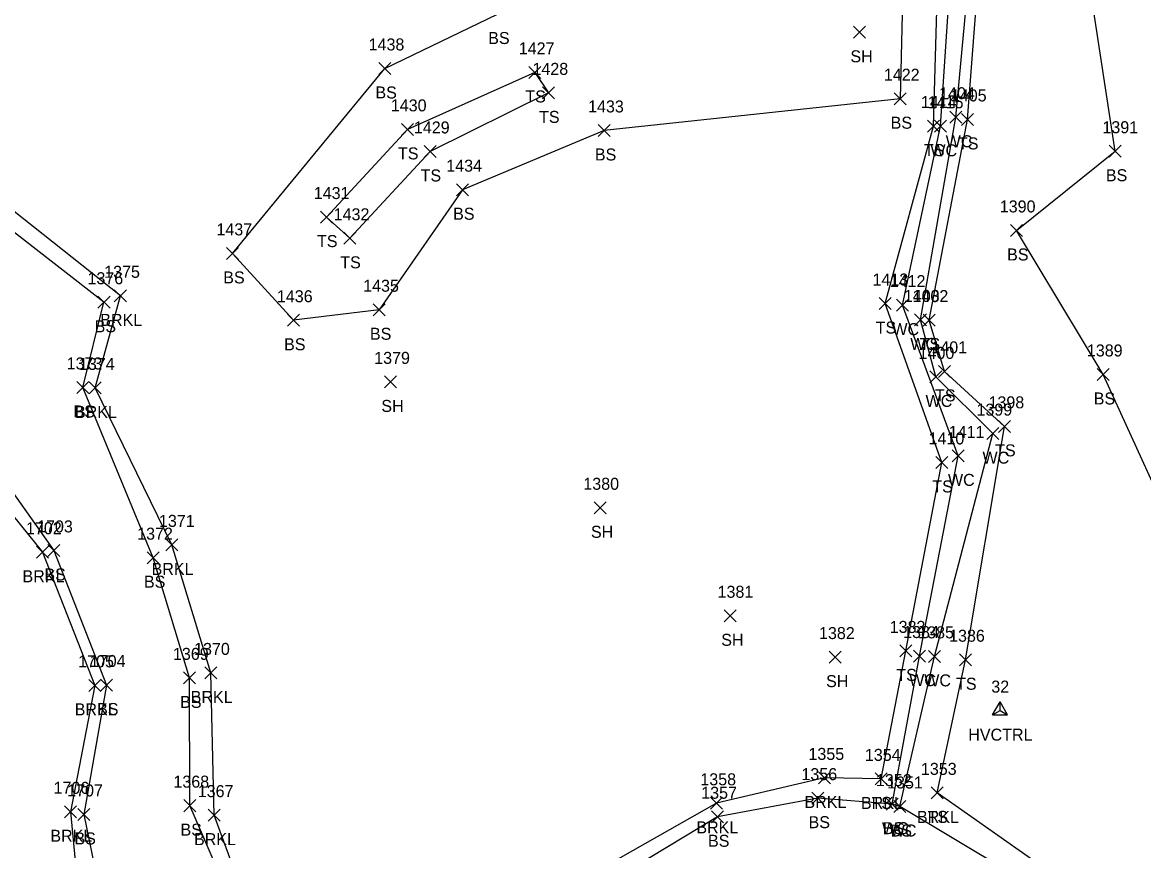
# Model space of a CAD drawing. Extents: x 1754529 to 1755810, y 621660 to 624656.
# Drawn here: x 1755027.6 to 1755214.3, y 623948.9 to 624086.9 of the extents above; entities that cross this region are included whole.
import ezdxf

# ---------------------------------------------------------------- set-up
doc = ezdxf.new("R2010")
doc.units = 0
for name, color, linetype in [('C_A', 7, 'Continuous'), ('C_I', 7, 'Continuous'), ('CPSM', 7, 'Continuous'), ('L_A', 7, 'Continuous'), ('L_I', 7, 'Continuous'), ('L_TIC', 7, 'Continuous'), ('LAWE', 7, 'Continuous'), ('LELB', 7, 'Continuous')]:
    doc.layers.add(name, color=color, linetype=linetype)

msp = doc.modelspace()

# ---------------------------------------------------------------- linework, layer by layer
at = {"layer": 'CPSM'}
for p, q in [((1755189.18, 623971.5), (1755190.43, 623973.67)), ((1755191.68, 623971.5), (1755190.43, 623973.67)), ((1755190.43, 623972.22), (1755190.43, 623973.67)), ((1755189.18, 623971.5), (1755190.43, 623972.22)), ((1755189.18, 623971.5), (1755191.68, 623971.5)), ((1755190.43, 623972.22), (1755190.43, 623972.22)), ((1755190.43, 623972.22), (1755191.68, 623971.5))]:
    msp.add_line(p, q, dxfattribs=at)
at = {"layer": 'L_TIC'}
for points in [[(1755166.02, 624084.22), (1755168.02, 624086.22)], [(1755168.02, 624084.22), (1755166.02, 624086.22)], [(1755086.97, 624078.2), (1755088.97, 624080.2)], [(1755088.97, 624078.2), (1755086.97, 624080.2)], [(1755111.97, 624077.54), (1755113.97, 624079.54)], [(1755113.97, 624077.54), (1755111.97, 624079.54)], [(1755111.97, 624077.54), (1755113.97, 624079.54)], [(1755113.97, 624077.54), (1755111.97, 624079.54)], [(1755114.25, 624074.13), (1755116.25, 624076.13)], [(1755116.25, 624074.13), (1755114.25, 624076.13)], [(1755172.76, 624073.16), (1755174.76, 624075.16)], [(1755174.76, 624073.16), (1755172.76, 624075.16)], [(1755182.05, 624070.07), (1755184.05, 624072.07)], [(1755184.05, 624070.07), (1755182.05, 624072.07)], [(1755184, 624069.71), (1755186, 624071.71)], [(1755186, 624069.71), (1755184, 624071.71)], [(1755090.76, 624068.05), (1755092.76, 624070.05)], [(1755092.76, 624068.05), (1755090.76, 624070.05)], [(1755123.51, 624067.87), (1755125.51, 624069.87)], [(1755125.51, 624067.87), (1755123.51, 624069.87)], [(1755178.35, 624068.6), (1755180.35, 624070.6)], [(1755180.35, 624068.6), (1755178.35, 624070.6)], [(1755179.5, 624068.56), (1755181.5, 624070.56)], [(1755181.5, 624068.56), (1755179.5, 624070.56)], [(1755094.53, 624064.37), (1755096.53, 624066.37)], [(1755096.53, 624064.37), (1755094.53, 624066.37)], [(1755208.59, 624064.41), (1755210.59, 624066.41)], [(1755210.59, 624064.41), (1755208.59, 624066.41)], [(1755099.91, 624058), (1755101.91, 624060)], [(1755101.91, 624058), (1755099.91, 624060)], [(1755077.28, 624053.44), (1755079.28, 624055.44)], [(1755079.28, 624053.44), (1755077.28, 624055.44)], [(1755192.15, 624051.21), (1755194.15, 624053.21)], [(1755194.15, 624051.21), (1755192.15, 624053.21)], [(1755081.15, 624049.9), (1755083.15, 624051.9)], [(1755083.15, 624049.9), (1755081.15, 624051.9)], [(1755081.15, 624049.9), (1755083.15, 624051.9)], [(1755083.15, 624049.9), (1755081.15, 624051.9)], [(1755061.63, 624047.39), (1755063.63, 624049.39)], [(1755063.63, 624047.39), (1755061.63, 624049.39)], [(1755042.94, 624040.32), (1755044.94, 624042.32)], [(1755044.94, 624040.32), (1755042.94, 624042.32)], [(1755040.22, 624039.25), (1755042.22, 624041.25)], [(1755042.22, 624039.25), (1755040.22, 624041.25)], [(1755086.06, 624038), (1755088.06, 624040)], [(1755088.06, 624038), (1755086.06, 624040)], [(1755170.3, 624039.04), (1755172.3, 624041.04)], [(1755172.3, 624039.04), (1755170.3, 624041.04)], [(1755173.17, 624038.77), (1755175.17, 624040.77)], [(1755175.17, 624038.77), (1755173.17, 624040.77)], [(1755071.75, 624036.25), (1755073.75, 624038.25)], [(1755073.75, 624036.25), (1755071.75, 624038.25)], [(1755176.17, 624036.31), (1755178.17, 624038.31)], [(1755178.17, 624036.31), (1755176.17, 624038.31)], [(1755177.62, 624036.28), (1755179.62, 624038.28)], [(1755179.62, 624036.28), (1755177.62, 624038.28)], [(1755178.71, 624026.81), (1755180.71, 624028.81)], [(1755180.71, 624026.81), (1755178.71, 624028.81)], [(1755180.19, 624027.74), (1755182.19, 624029.74)], [(1755182.19, 624027.74), (1755180.19, 624029.74)], [(1755206.57, 624027.22), (1755208.57, 624029.22)], [(1755208.57, 624027.22), (1755206.57, 624029.22)], [(1755036.69, 624025.06), (1755038.69, 624027.06)], [(1755038.69, 624025.06), (1755036.69, 624027.06)], [(1755038.74, 624024.98), (1755040.74, 624026.98)], [(1755040.74, 624024.98), (1755038.74, 624026.98)], [(1755087.91, 624025.98), (1755089.91, 624027.98)], [(1755089.91, 624025.98), (1755087.91, 624027.98)], [(1755188.19, 624017.36), (1755190.19, 624019.36)], [(1755190.19, 624017.36), (1755188.19, 624019.36)], [(1755190.18, 624018.58), (1755192.18, 624020.58)], [(1755192.18, 624018.58), (1755190.18, 624020.58)], [(1755182.44, 624013.66), (1755184.44, 624015.66)], [(1755184.44, 624013.66), (1755182.44, 624015.66)], [(1755179.73, 624012.57), (1755181.73, 624014.57)], [(1755181.73, 624012.57), (1755179.73, 624014.57)], [(1755122.81, 624005.01), (1755124.81, 624007.01)], [(1755124.81, 624005.01), (1755122.81, 624007.01)], [(1755051.5, 623998.83), (1755053.5, 624000.83)], [(1755053.5, 623998.83), (1755051.5, 624000.83)], [(1755030, 623997.61), (1755032, 623999.61)], [(1755032, 623997.61), (1755030, 623999.61)], [(1755031.85, 623997.91), (1755033.85, 623999.91)], [(1755033.85, 623997.91), (1755031.85, 623999.91)], [(1755048.43, 623996.7), (1755050.43, 623998.7)], [(1755050.43, 623996.7), (1755048.43, 623998.7)], [(1755144.5, 623987.02), (1755146.5, 623989.02)], [(1755146.5, 623987.02), (1755144.5, 623989.02)], [(1755161.96, 623980.14), (1755163.96, 623982.14)], [(1755163.96, 623980.14), (1755161.96, 623982.14)], [(1755173.73, 623981.17), (1755175.73, 623983.17)], [(1755175.73, 623981.17), (1755173.73, 623983.17)], [(1755175.98, 623980.31), (1755177.98, 623982.31)], [(1755177.98, 623980.31), (1755175.98, 623982.31)], [(1755178.49, 623980.26), (1755180.49, 623982.26)], [(1755180.49, 623980.26), (1755178.49, 623982.26)], [(1755183.68, 623979.7), (1755185.68, 623981.7)], [(1755185.68, 623979.7), (1755183.68, 623981.7)], [(1755054.45, 623976.68), (1755056.45, 623978.68)], [(1755056.45, 623976.68), (1755054.45, 623978.68)], [(1755058, 623977.5), (1755060, 623979.5)], [(1755060, 623977.5), (1755058, 623979.5)], [(1755038.69, 623975.43), (1755040.69, 623977.43)], [(1755040.69, 623975.43), (1755038.69, 623977.43)], [(1755040.63, 623975.49), (1755042.63, 623977.49)], [(1755042.63, 623975.49), (1755040.63, 623977.49)], [(1755160.2, 623960.01), (1755162.2, 623962.01)], [(1755162.2, 623960.01), (1755160.2, 623962.01)], [(1755169.6, 623959.85), (1755171.6, 623961.85)], [(1755171.6, 623959.85), (1755169.6, 623961.85)], [(1755169.6, 623959.85), (1755171.6, 623961.85)], [(1755171.6, 623959.85), (1755169.6, 623961.85)], [(1755178.93, 623957.52), (1755180.93, 623959.52)], [(1755180.93, 623957.52), (1755178.93, 623959.52)], [(1755178.93, 623957.52), (1755180.93, 623959.52)], [(1755180.93, 623957.52), (1755178.93, 623959.52)], [(1755142.2, 623955.78), (1755144.2, 623957.78)], [(1755144.2, 623955.78), (1755142.2, 623957.78)], [(1755159.09, 623956.64), (1755161.09, 623958.64)], [(1755161.09, 623956.64), (1755159.09, 623958.64)], [(1755171.44, 623955.64), (1755173.44, 623957.64)], [(1755173.44, 623955.64), (1755171.44, 623957.64)], [(1755171.44, 623955.64), (1755173.44, 623957.64)], [(1755173.44, 623955.64), (1755171.44, 623957.64)], [(1755034.65, 623954.37), (1755036.65, 623956.37)], [(1755036.65, 623954.37), (1755034.65, 623956.37)], [(1755036.86, 623953.93), (1755038.86, 623955.93)], [(1755038.86, 623953.93), (1755036.86, 623955.93)], [(1755054.52, 623955.39), (1755056.52, 623957.39)], [(1755056.52, 623955.39), (1755054.52, 623957.39)], [(1755058.57, 623953.81), (1755060.57, 623955.81)], [(1755060.57, 623953.81), (1755058.57, 623955.81)], [(1755172.74, 623955.25), (1755174.74, 623957.25)], [(1755174.74, 623955.25), (1755172.74, 623957.25)], [(1755172.74, 623955.25), (1755174.74, 623957.25)], [(1755174.74, 623955.25), (1755172.74, 623957.25)], [(1755142.35, 623953.54), (1755144.35, 623955.54)], [(1755144.35, 623953.54), (1755142.35, 623955.54)]]:
    msp.add_lwpolyline(points, dxfattribs=at)
at = {"layer": 'LAWE'}
for points in [[(1755173.74, 623956.25), (1755179.49, 623981.26), (1755189.19, 624018.36), (1755179.71, 624027.81), (1755177.17, 624037.31), (1755183.05, 624071.07), (1755186.59, 624109.3), (1755195.76, 624123.49), (1755204.15, 624140.63), (1755199.7, 624157.52), (1755189.07, 624181.84), (1755178.94, 624196.44), (1755167.9, 624207.95), (1755156.07, 624245.11), (1755149.51, 624271.99), (1755152.32, 624294.92), (1755143.66, 624313.83), (1755149.45, 624329.22), (1755168.42, 624354.45), (1755209.86, 624368.35), (1755209.13, 624369.86)], [(1755172.44, 623956.64), (1755176.98, 623981.31), (1755183.44, 624014.66), (1755174.17, 624039.77), (1755180.5, 624069.56), (1755183.04, 624107.8), (1755193.55, 624125.22), (1755195.6, 624144.75), (1755194.59, 624151.24), (1755197.16, 624154.94), (1755178.66, 624184.32), (1755154.86, 624214.79), (1755145.09, 624237.93), (1755132.18, 624249.28), (1755138.85, 624266.04), (1755143.77, 624297.7), (1755137.75, 624306.01)], [(1755170.6, 623960.85), (1755161.2, 623961.01), (1755143.2, 623956.78), (1755119.33, 623943.27), (1755096.2, 623926.93), (1755077.94, 623936.98), (1755067.58, 623933.06), (1755059.57, 623954.81), (1755059, 623978.5), (1755052.5, 623999.83), (1755039.74, 624025.98), (1755043.94, 624041.32), (1755011.46, 624067.07)], [(1755008.39, 624026.55), (1755031, 623998.61), (1755039.69, 623976.43), (1755035.65, 623955.37), (1755037.46, 623936.07), (1755049.82, 623913.03), (1755070.37, 623897.42), (1755092.38, 623883.1), (1755098.8, 623882.29), (1755109.49, 623891.87), (1755119.28, 623910.59), (1755131.22, 623922.86), (1755147.91, 623930.97), (1755162.29, 623935.63), (1755179.51, 623935.92), (1755189.79, 623927.6), (1755194.4, 623918.88), (1755192.05, 623908.18), (1755200.59, 623896.44), (1755204.82, 623894.29), (1755230.46, 623916.2)], [(1755370.87, 623791.95), (1755363.68, 623808), (1755365.74, 623820.69), (1755355.03, 623846.72), (1755346.68, 623853.51), (1755335.09, 623877.41), (1755323.56, 623896.77), (1755319.21, 623906.81), (1755286.2, 623944.29), (1755265.65, 623945.4), (1755241.6, 623939.51), (1755210.27, 623937.23), (1755179.93, 623958.52)]]:
    msp.add_lwpolyline(points, dxfattribs=at)
at = {"layer": 'LELB'}
for points in [[(1755179.93, 623958.52), (1755184.68, 623980.7), (1755191.18, 624019.58), (1755181.19, 624028.74), (1755178.62, 624037.28), (1755185, 624070.71), (1755187.96, 624108.96), (1755197.92, 624122.33), (1755209.55, 624141.51), (1755204.36, 624157.97), (1755190.25, 624182.31), (1755180.73, 624197.48), (1755169.22, 624208.69), (1755158.15, 624245.97), (1755151.05, 624272.57), (1755153.5, 624295.6), (1755146.12, 624314.43), (1755150.89, 624328.89), (1755170.15, 624351.46)], [(1755170.6, 623960.85), (1755174.73, 623982.17), (1755180.73, 624013.57), (1755171.3, 624040.04), (1755179.35, 624069.6), (1755180.41, 624106.3), (1755192.02, 624127.09), (1755193.84, 624144.56), (1755192.95, 624151.67), (1755195.38, 624154.8), (1755176.76, 624182.9), (1755153.26, 624214.03), (1755142.49, 624236.72), (1755135.31, 624238.73)], [(1755180.41, 624106.3), (1755174.28, 624095.36), (1755173.76, 624074.16), (1755124.51, 624068.87), (1755100.91, 624059), (1755087.06, 624039), (1755072.75, 624037.25), (1755062.63, 624048.39), (1755087.97, 624079.2), (1755106.75, 624088.27), (1755068.94, 624107.54), (1755034.87, 624118.61), (1755022.08, 624140.4), (1755014.83, 624155.53)], [(1755286.2, 623944.29), (1755267.63, 623949.34), (1755239.18, 623957.43), (1755232.04, 623971.1), (1755221.75, 623997.22), (1755207.57, 624028.22), (1755193.15, 624052.21), (1755209.59, 624065.41), (1755204.71, 624097.4), (1755197.92, 624122.33)], [(1755112.97, 624078.54), (1755091.76, 624069.05), (1755078.28, 624054.44), (1755082.15, 624050.9)], [(1755112.97, 624078.54), (1755115.25, 624075.13), (1755095.53, 624065.37), (1755082.15, 624050.9)], [(1755241.68, 623936.2), (1755210.26, 623934.38), (1755173.74, 623956.25), (1755172.44, 623956.64), (1755160.09, 623957.64), (1755143.35, 623954.54), (1755120.93, 623940.96), (1755095.74, 623923.84), (1755077.07, 623934.54), (1755066.71, 623930.46), (1755055.52, 623956.39), (1755055.45, 623977.68), (1755049.43, 623997.7), (1755037.69, 624026.06), (1755041.22, 624040.25), (1755009.04, 624065.23)], [(1755012.46, 624027.69), (1755032.85, 623998.91), (1755041.63, 623976.49), (1755037.86, 623954.93), (1755041.45, 623937.31), (1755053.86, 623916.81), (1755074.13, 623900.5), (1755093.54, 623886.18), (1755103.13, 623891.7), (1755116.15, 623912.87), (1755129.67, 623924.89), (1755147.31, 623933.94), (1755162.66, 623937.91), (1755180.24, 623937.43), (1755191.16, 623929.62), (1755197.64, 623918.34), (1755197.2, 623907.93), (1755204.31, 623898.91), (1755229.99, 623917.44)]]:
    msp.add_lwpolyline(points, dxfattribs=at)

# ---------------------------------------------------------------- texts
at = {"layer": 'C_A'}
msp.add_text('HVCTRL', height=2, dxfattribs=at).set_placement((1755185.12, 623967.22))
at = {"layer": 'C_I'}
msp.add_text('32', height=2, dxfattribs=at).set_placement((1755188.96, 623975.22))
at = {"layer": 'L_A'}
for s, p in [('BS', (1755105.19, 624083.27)), ('SH', (1755165.5, 624080.22)), ('BS', (1755086.41, 624074.2)), ('TS', (1755111.38, 624073.54)), ('TS', (1755111.38, 624073.54)), ('TS', (1755113.66, 624070.13)), ('BS', (1755172.2, 624069.16)), ('WC', (1755181.36, 624066.07)), ('TS', (1755090.17, 624064.05)), ('TS', (1755177.76, 624064.6)), ('WC', (1755178.81, 624064.56)), ('TS', (1755183.41, 624065.71)), ('BS', (1755122.95, 624063.87)), ('TS', (1755093.94, 624060.37)), ('BS', (1755208.03, 624060.41)), ('BS', (1755099.35, 624054)), ('TS', (1755076.69, 624049.44)), ('BS', (1755191.59, 624047.21)), ('TS', (1755080.56, 624045.9)), ('TS', (1755080.56, 624045.9)), ('BS', (1755061.07, 624043.39)), ('BRKL', (1755040.59, 624036.32)), ('BS', (1755039.66, 624035.25)), ('TS', (1755169.71, 624035.04)), ('WC', (1755172.48, 624034.77)), ('BS', (1755071.2, 624032.25)), ('BS', (1755085.5, 624034)), ('WC', (1755175.47, 624032.31)), ('TS', (1755177.03, 624032.28)), ('WC', (1755178.01, 624022.81)), ('TS', (1755179.59, 624023.74)), ('BS', (1755206.01, 624023.22)), ('BS', (1755036.14, 624021.06)), ('BRKL', (1755036.39, 624020.98)), ('SH', (1755087.4, 624021.98)), ('TS', (1755189.59, 624014.58)), ('WC', (1755187.49, 624013.36)), ('TS', (1755179.14, 624008.57)), ('WC', (1755181.74, 624009.66)), ('SH', (1755122.3, 624001.01)), ('BRKL', (1755027.65, 623993.61)), ('BS', (1755031.29, 623993.91)), ('BRKL', (1755049.14, 623994.83)), ('BS', (1755047.87, 623992.7)), ('SH', (1755143.99, 623983.02)), ('SH', (1755161.45, 623976.14)), ('TS', (1755173.14, 623977.17)), ('WC', (1755175.28, 623976.31)), ('WC', (1755177.79, 623976.26)), ('TS', (1755183.09, 623975.7)), ('BS', (1755053.89, 623972.68)), ('BRKL', (1755055.65, 623973.5)), ('BRKL', (1755036.34, 623971.43)), ('BS', (1755040.07, 623971.49)), ('BRKL', (1755157.85, 623956.01)), ('BRKL', (1755167.25, 623955.85)), ('TS', (1755169.01, 623955.85)), ('BS', (1755158.53, 623952.64)), ('BRKL', (1755176.58, 623953.52)), ('TS', (1755178.34, 623953.52)), ('BRKL', (1755032.29, 623950.37)), ('BS', (1755053.96, 623951.39)), ('BRKL', (1755139.85, 623951.78)), ('WC', (1755170.75, 623951.64)), ('BS', (1755170.89, 623951.64)), ('WC', (1755172.04, 623951.25)), ('BS', (1755172.18, 623951.25)), ('BS', (1755036.3, 623949.93)), ('BRKL', (1755056.21, 623949.81)), ('BS', (1755141.79, 623949.54))]:
    msp.add_text(s, height=2, dxfattribs=at).set_placement(p)
at = {"layer": 'L_I'}
for s, p in [('1438', (1755085.28, 624082.2)), ('1427', (1755110.28, 624081.54)), ('1427', (1755110.28, 624081.54)), ('1428', (1755112.56, 624078.13)), ('1422', (1755171.07, 624077.16)), ('1404', (1755180.28, 624074.07)), ('1405', (1755182.23, 624073.71)), ('1430', (1755088.98, 624072.05)), ('1433', (1755121.82, 624071.87)), ('1414', (1755177.23, 624072.6)), ('1415', (1755178.38, 624072.56)), ('1429', (1755092.82, 624068.37)), ('1391', (1755207.46, 624068.41)), ('1434', (1755098.21, 624062)), ('1431', (1755076.15, 624057.44)), ('1390', (1755190.37, 624055.21)), ('1432', (1755079.46, 624053.9)), ('1432', (1755079.46, 624053.9)), ('1437', (1755059.94, 624051.39)), ('1375', (1755041.25, 624044.32)), ('1376', (1755038.47, 624043.25)), ('1435', (1755084.37, 624042)), ('1413', (1755169.18, 624043.04)), ('1412', (1755172.04, 624042.77)), ('1436', (1755070.01, 624040.25)), ('1403', (1755174.4, 624040.31)), ('1402', (1755175.85, 624040.28)), ('1400', (1755176.85, 624030.81)), ('1401', (1755178.98, 624031.74)), ('1389', (1755204.87, 624031.22)), ('1373', (1755035, 624029.06)), ('1374', (1755037.05, 624028.98)), ('1379', (1755086.21, 624029.98)), ('1399', (1755186.49, 624021.36)), ('1398', (1755188.49, 624022.58)), ('1411', (1755181.88, 624017.66)), ('1410', (1755178.51, 624016.57)), ('1380', (1755121.03, 624009.01)), ('1371', (1755050.37, 624002.83)), ('1702', (1755028.23, 624001.61)), ('1703', (1755030.08, 624001.91)), ('1372', (1755046.74, 624000.7)), ('1381', (1755143.38, 623991.02)), ('1382', (1755160.27, 623984.14)), ('1383', (1755172.04, 623985.17)), ('1384', (1755174.28, 623984.31)), ('1385', (1755176.79, 623984.26)), ('1386', (1755181.93, 623983.7)), ('1369', (1755052.7, 623980.68)), ('1370', (1755056.22, 623981.5)), ('1705', (1755036.92, 623979.43)), ('1704', (1755038.86, 623979.49)), ('1355', (1755158.51, 623964.01)), ('1354', (1755167.91, 623963.85)), ('1354', (1755167.91, 623963.85)), ('1353', (1755177.24, 623961.52)), ('1353', (1755177.24, 623961.52)), ('1368', (1755052.78, 623959.39)), ('1358', (1755140.51, 623959.78)), ('1356', (1755157.34, 623960.64)), ('1352', (1755169.75, 623959.64)), ('1352', (1755169.75, 623959.64)), ('1706', (1755032.82, 623958.37)), ('1707', (1755035.09, 623957.93)), ('1367', (1755056.83, 623957.81)), ('1357', (1755140.66, 623957.54)), ('1351', (1755171.61, 623959.25)), ('1351', (1755171.61, 623959.25))]:
    msp.add_text(s, height=2, dxfattribs=at).set_placement(p)

doc.saveas('drawing.dxf')
